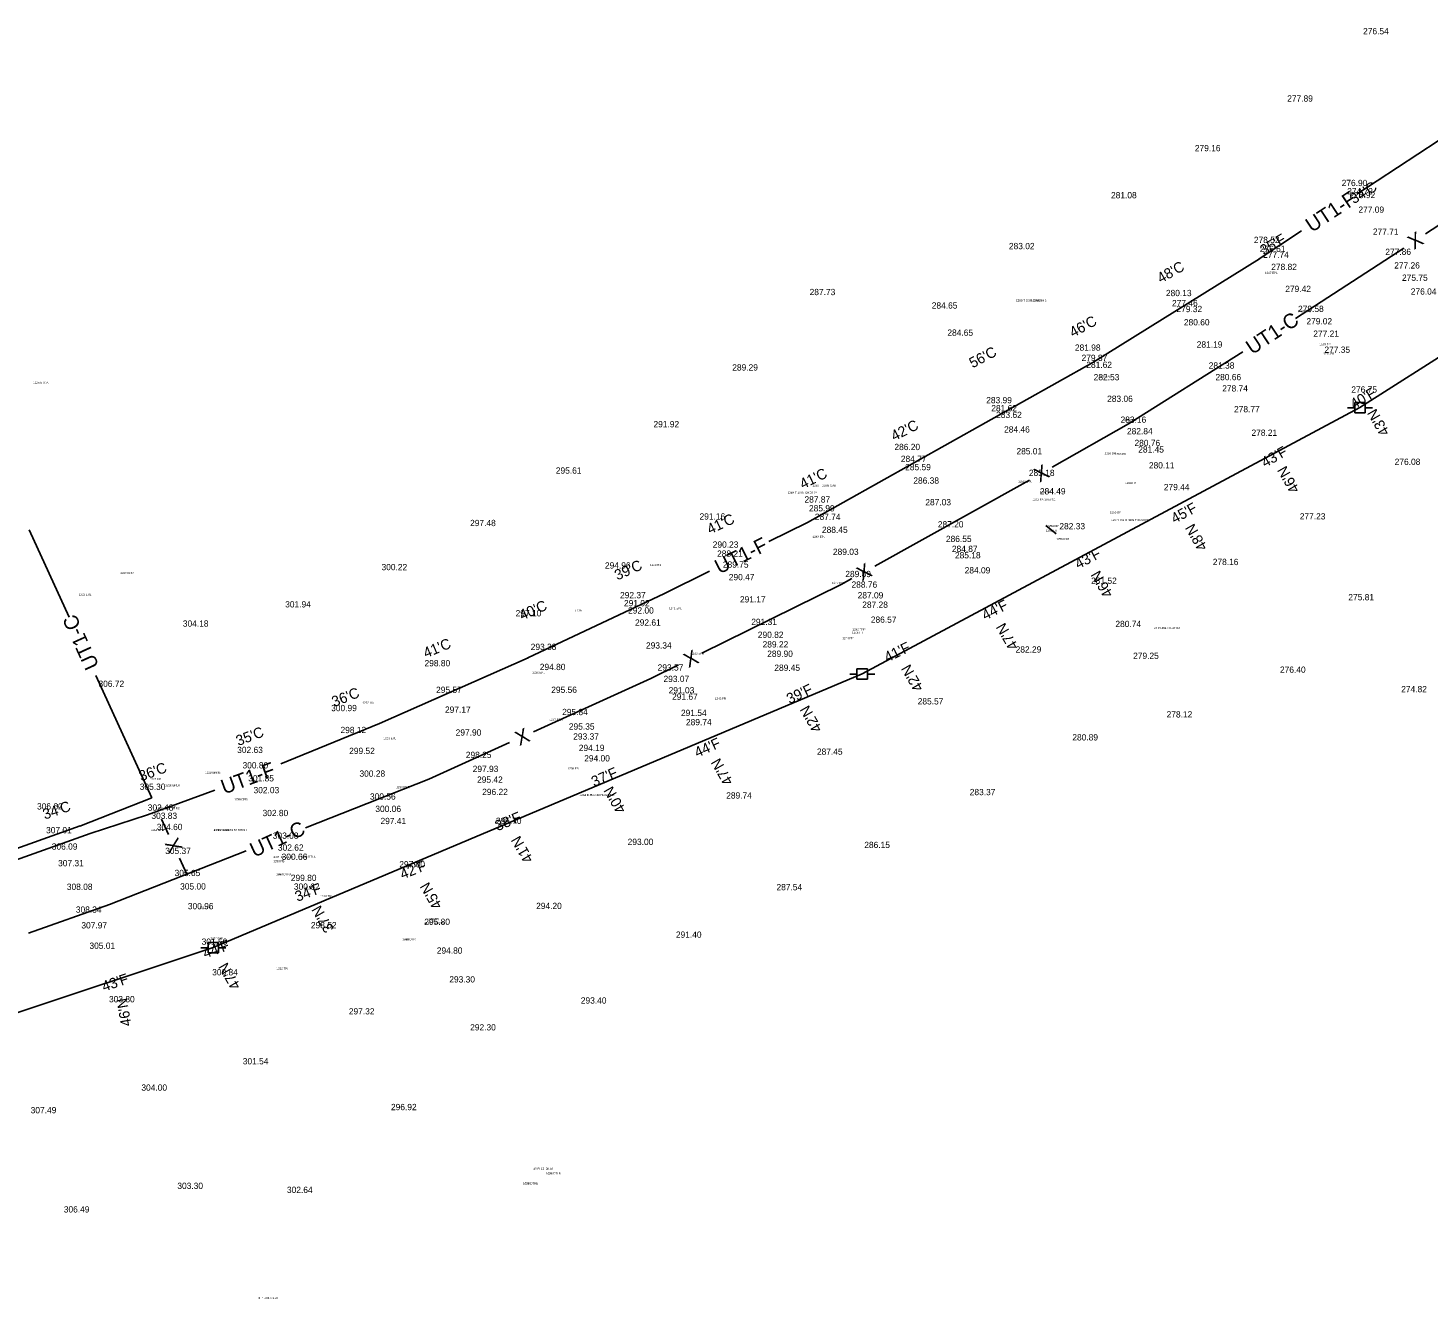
# Model space of a CAD drawing. Extents: x 49683 to 58852, y 49596 to 54801.
# Drawn here: x 51586 to 52255, y 49928 to 50535 of the extents above; entities that cross this region are included whole.
import ezdxf

# ---------------------------------------------------------------- set-up
doc = ezdxf.new("R2010")
doc.units = 0
for name, color, linetype in [('Level 10', 7, 'Continuous'), ('Level 2', 7, 'Continuous'), ('Level 3', 7, 'Continuous'), ('Level 32', 7, 'Continuous'), ('Level 4', 7, 'Continuous'), ('Level 48', 7, 'Continuous'), ('Level 51', 7, 'Continuous'), ('Level 53', 7, 'Continuous'), ('Level 56', 7, 'Continuous'), ('Level 58', 7, 'Continuous'), ('Level 59', 7, 'Continuous'), ('Level 60', 7, 'Continuous'), ('Level 61', 7, 'Continuous'), ('Level 8', 7, 'Continuous'), ('Level 9', 7, 'Continuous')]:
    doc.layers.add(name, color=color, linetype=linetype)

# ---------------------------------------------------------------- blocks, each defined once
blk = doc.blocks.new('PP')
at = {"layer": 'Level 9'}
for p, q in [((2.53, 2.45), (-2.47, 2.45)), ((-2.47, 2.45), (-2.47, -2.55)), ((2.53, -2.55), (2.53, 2.45)), ((-5.91, -0.11), (-2.44, -0.11)), ((-2.47, -2.55), (2.53, -2.55)), ((2.45, -0.11), (6.09, -0.11))]:
    blk.add_line(p, q, dxfattribs=at)

msp = doc.modelspace()

# ---------------------------------------------------------------- linework, layer by layer
at = {"layer": 'Level 10'}
for p, q in [((52222.33, 50353.9), (52441.61, 50493.85)), ((52222.33, 50353.9), (51984.4, 50226.57)), ((51674.22, 50095.74), (51984.4, 50226.57)), ((51674.22, 50095.74), (51498.02, 50037.11))]:
    msp.add_line(p, q, dxfattribs=at)
at = {"layer": 'Level 2'}
for p, q in [((52220.92, 50455.82), (52259.66, 50481.44)), ((52174.21, 50424.93), (52194.48, 50438.34)), ((52253.74, 50436.92), (52260.12, 50441.07)), ((52094.67, 50375.45), (52174.32, 50425.01)), ((52191.57, 50396.46), (52243.3, 50430.12)), ((52111.7, 50346.13), (52166.43, 50380.5)), ((51958.35, 50298.99), (52094.67, 50375.45)), ((52075.2, 50325.36), (52111.7, 50346.13)), ((51990.42, 50278.12), (52061.21, 50317.41)), ((52061.25, 50317.43), (52064.37, 50319.21)), ((51939.84, 50289.78), (51958.35, 50298.99)), ((51889.92, 50264.94), (51911.46, 50275.66)), ((51974.39, 50269.22), (51979.53, 50272.07)), ((51824.58, 50234.17), (51889.92, 50264.94)), ((51907.82, 50236.42), (51974.39, 50269.22)), ((51753.66, 50202.89), (51824.69, 50234.22)), ((51883.33, 50224.35), (51896.64, 50230.91)), ((51827.24, 50198.92), (51883.33, 50224.35)), ((51706.58, 50183.59), (51753.66, 50202.89)), ((51777.28, 50176.27), (51815.9, 50193.78)), ((51718.4, 50152.94), (51777.28, 50176.27)), ((51642.76, 50159.18), (51674.98, 50170.97)), ((51615.33, 50150.2), (51642.76, 50159.18)), ((51649.56, 50157.08), (51652.91, 50149.76)), ((51519.2, 50116.09), (51615.33, 50150.2)), ((51624.57, 50116.34), (51689.98, 50141.89)), ((51658.09, 50138.43), (51661.61, 50130.73)), ((51585.87, 50102.61), (51624.57, 50116.34))]:
    msp.add_line(p, q, dxfattribs=at)
at = {"layer": 'Level 3'}
for p, q in [((51586.25, 50295.45), (51605.36, 50253.67)), ((51618.09, 50225.85), (51644.91, 50167.23)), ((51610.53, 50153.8), (51644.91, 50167.23)), ((51517.65, 50120.85), (51610.67, 50153.85))]:
    msp.add_line(p, q, dxfattribs=at)
at = {"layer": 'Level 8'}
msp.add_line((52072.23, 50297.54), (52077.21, 50293.52), dxfattribs=at)

# ---------------------------------------------------------------- block references
at = {"layer": 'Level 10'}
for p in [(52222.33, 50353.9), (51984.4, 50226.57), (51674.22, 50095.74)]:
    msp.add_blockref('PP', p, dxfattribs=at)

# ---------------------------------------------------------------- texts
at = {"layer": 'Level 2'}
for s, rotation, p in [('UT1-F', 33.47604, (52199.33, 50437.35)), ('UT1-C', 33.47604, (52170.82, 50378.92)), ('UT1-F', 26.45366, (51916.16, 50274.09)), ('UT1-F', 20.1051, (51679.47, 50168.89)), ('UT1-C', 24.61141, (51693.8, 50138.67))]:
    msp.add_text(s, height=7, rotation=rotation, dxfattribs=at).set_placement(p)
at = {"layer": 'Level 32'}
for s, p in [('276.54', (52223.85, 50532.28)), ('277.89', (52187.59, 50500.13)), ('279.16', (52143.44, 50476.41)), ('276.90', (52213.61, 50459.74)), ('274.72', (52216.26, 50455.76)), ('275.92', (52217.39, 50453.98)), ('281.08', (52103.37, 50453.89)), ('277.09', (52221.62, 50446.98)), ('277.71', (52228.54, 50436.46)), ('283.02', (52054.56, 50429.58)), ('278.52', (52171.66, 50432.5)), ('276.61', (52174.46, 50428.23)), ('277.74', (52176.09, 50425.44)), ('277.86', (52234.49, 50426.85)), ('278.82', (52179.95, 50419.62)), ('277.26', (52238.73, 50420.34)), ('275.75', (52242.45, 50414.45)), ('287.73', (51959.29, 50407.61)), ('280.13', (52129.6, 50407.13)), ('279.42', (52186.65, 50409.09)), ('276.04', (52246.66, 50407.86)), ('284.65', (52017.68, 50401.18)), ('277.46', (52132.53, 50402.32)), ('279.32', (52134.64, 50399.48)), ('279.58', (52192.77, 50399.55)), ('284.65', (52025.15, 50388.18)), ('280.60', (52138.2, 50393.15)), ('279.02', (52196.77, 50393.62)), ('277.21', (52200.05, 50387.68)), ('281.98', (52086.1, 50381.02)), ('281.19', (52144.34, 50382.52)), ('279.87', (52089.3, 50376.15)), ('277.35', (52205.36, 50380.03)), ('289.29', (51922.32, 50371.56)), ('281.62', (52091.56, 50372.84)), ('281.38', (52150.07, 50372.49)), ('280.66', (52153.29, 50366.94)), ('282.53', (52095.08, 50366.91)), ('278.74', (52156.52, 50361.55)), ('276.75', (52218.23, 50361.01)), ('283.99', (52043.71, 50355.92)), ('283.06', (52101.51, 50356.58)), ('281.62', (52046.14, 50352.1)), ('283.62', (52048.45, 50348.9)), ('278.77', (52162.17, 50351.6)), ('291.92', (51884.65, 50344.42)), ('284.46', (52052.25, 50341.93)), ('283.16', (52107.93, 50346.57)), ('282.84', (52111, 50341.11)), ('278.21', (52170.52, 50340.35)), ('286.20', (51999.83, 50333.53)), ('280.76', (52114.58, 50335.45)), ('284.77', (52002.9, 50327.86)), ('285.01', (52058.17, 50331.48)), ('281.45', (52116.38, 50332.35)), ('295.61', (51838, 50322.27)), ('285.59', (52004.97, 50323.89)), ('285.18', (52064.11, 50321.15)), ('280.11', (52121.47, 50324.75)), ('276.08', (52238.96, 50326.46)), ('286.38', (52008.88, 50317.48)), ('279.44', (52128.62, 50314.36)), ('287.87', (51956.84, 50308.44)), ('287.03', (52014.61, 50307.11)), ('284.49', (52069.37, 50312.34)), ('291.16', (51906.69, 50300.31)), ('285.99', (51959, 50304.22)), ('287.74', (51961.81, 50300.15)), ('277.23', (52193.58, 50300.37)), ('297.48', (51797.01, 50297.19)), ('288.45', (51965.2, 50293.96)), ('287.20', (52020.58, 50296.56)), ('282.33', (52078.69, 50295.66)), ('290.23', (51912.99, 50286.87)), ('286.55', (52024.45, 50289.58)), ('288.21', (51915.06, 50282.53)), ('289.03', (51970.45, 50283.44)), ('284.87', (52027.31, 50284.82)), ('285.18', (52028.77, 50281.76)), ('300.22', (51754.67, 50276.11)), ('294.96', (51861.47, 50276.9)), ('289.75', (51917.84, 50277.32)), ('284.09', (52033.4, 50274.57)), ('278.16', (52151.99, 50278.56)), ('290.47', (51920.66, 50271.33)), ('289.09', (51976.36, 50272.8)), ('288.76', (51979.33, 50267.73)), ('281.52', (52093.84, 50269.59)), ('292.37', (51868.69, 50262.7)), ('291.17', (51925.99, 50260.69)), ('287.09', (51982.26, 50262.61)), ('275.81', (52216.81, 50261.73)), ('301.94', (51708.62, 50258.31)), ('297.10', (51818.78, 50254.07)), ('291.02', (51870.57, 50258.9)), ('292.00', (51872.53, 50255.38)), ('287.28', (51984.45, 50258.13)), ('304.18', (51659.71, 50249.1)), ('292.61', (51875.85, 50249.6)), ('291.31', (51931.41, 50249.91)), ('286.57', (51988.56, 50250.97)), ('280.74', (52105.46, 50248.92)), ('290.82', (51934.55, 50243.76)), ('293.38', (51825.99, 50237.97)), ('293.34', (51881.08, 50238.66)), ('289.22', (51936.82, 50239.17)), ('289.90', (51939.03, 50234.69)), ('282.29', (52057.78, 50236.75)), ('279.25', (52113.93, 50233.71)), ('298.80', (51775.23, 50230.17)), ('294.80', (51830.31, 50228.36)), ('293.57', (51886.66, 50228.13)), ('289.45', (51942.43, 50228)), ('276.40', (52184.12, 50227.06)), ('306.72', (51619.38, 50220.33)), ('293.07', (51889.46, 50222.65)), ('295.57', (51780.75, 50217.43)), ('295.56', (51835.8, 50217.47)), ('291.03', (51891.91, 50217.21)), ('291.67', (51893.55, 50214.15)), ('274.82', (52242.08, 50217.78)), ('300.99', (51730.6, 50208.72)), ('297.17', (51785.01, 50207.95)), ('295.84', (51841.01, 50206.83)), ('291.54', (51897.8, 50206.4)), ('285.57', (52010.95, 50211.93)), ('295.35', (51844.22, 50199.9)), ('289.74', (51900.2, 50202.01)), ('278.12', (52129.94, 50205.7)), ('298.12', (51735.06, 50198.22)), ('297.90', (51790.11, 50197.03)), ('293.37', (51846.31, 50195.14)), ('280.89', (52084.87, 50194.72)), ('302.63', (51685.68, 50188.71)), ('299.52', (51739.2, 50188.26)), ('298.25', (51794.96, 50186.34)), ('294.19', (51848.96, 50189.68)), ('287.45', (51962.79, 50187.87)), ('300.80', (51688.23, 50181.35)), ('297.93', (51798.25, 50179.63)), ('294.00', (51851.56, 50184.68)), ('301.85', (51690.97, 50175.14)), ('300.28', (51744.13, 50177.38)), ('295.42', (51800.34, 50174.5)), ('305.30', (51639.11, 50171.11)), ('302.03', (51693.5, 50169.5)), ('300.56', (51749.15, 50166.43)), ('296.22', (51802.78, 50168.61)), ('289.74', (51919.43, 50166.94)), ('283.37', (52035.83, 50168.56)), ('306.62', (51590, 50161.72)), ('302.48', (51642.93, 50161.14)), ('300.06', (51751.72, 50160.52)), ('303.83', (51644.68, 50157.23)), ('302.80', (51697.8, 50158.54)), ('297.41', (51754.18, 50154.73)), ('295.70', (51809.31, 50154.81)), ('307.01', (51594.33, 50150.35)), ('304.60', (51647.24, 50151.87)), ('303.08', (51702.7, 50147.71)), ('306.09', (51597.06, 50142.51)), ('305.37', (51651.26, 50140.45)), ('302.62', (51705.15, 50142.01)), ('293.00', (51872.32, 50144.76)), ('286.15', (51985.42, 50143.28)), ('307.31', (51600.07, 50134.58)), ('300.66', (51706.93, 50137.63)), ('297.00', (51763.17, 50134.05)), ('305.65', (51655.76, 50129.88)), ('299.80', (51711.33, 50127.55)), ('308.08', (51604.26, 50123.28)), ('305.00', (51658.41, 50123.45)), ('300.62', (51712.79, 50123.35)), ('287.54', (51943.46, 50123.1)), ('300.96', (51662.09, 50114.02)), ('294.20', (51828.56, 50114.13)), ('308.34', (51608.57, 50112.35)), ('295.80', (51775.12, 50106.54)), ('307.97', (51611.21, 50104.85)), ('298.52', (51720.91, 50104.92)), ('291.40', (51895.38, 50100.39)), ('305.01', (51615.06, 50095.1)), ('301.50', (51668.7, 50097.03)), ('294.80', (51781.09, 50092.78)), ('300.84', (51673.72, 50082.42)), ('293.30', (51787.07, 50079.02)), ('303.80', (51624.42, 50069.53)), ('293.40', (51849.94, 50068.93)), ('297.32', (51739.04, 50063.74)), ('292.30', (51797.03, 50056.09)), ('301.54', (51688.35, 50039.86)), ('304.00', (51639.89, 50027.27)), ('307.49', (51586.97, 50016.49)), ('296.92', (51759.19, 50017.98)), ('303.30', (51657.08, 49980.32)), ('302.64', (51709.47, 49978.39)), ('306.49', (51602.79, 49969.06))]:
    msp.add_text(s, height=3, dxfattribs=at).set_placement(p)
at = {"layer": 'Level 4'}
for s, rotation, p in [('X', 33.05568, (52248.14, 50429.1)), ('X', 29.63146, (52069.14, 50317.89)), ('X', 29.03259, (51984.29, 50270.71)), ('UT1-C', 114.58439, (51619.82, 50230.49)), ('X', 26.22879, (51901.33, 50229.32)), ('X', 24.39066, (51820.53, 50192.04)), ('X', 114.58439, (51659.82, 50143.07))]:
    msp.add_text(s, height=7, rotation=rotation, dxfattribs=at).set_placement(p)
at = {"layer": 'Level 48'}
for s, rotation, p in [("34'C", 31.24615, (52219.41, 50451.04)), ("35'F", 30.37114, (52176.45, 50426.49)), ("48'C", 29.49614, (52127.19, 50413.14)), ("46'C", 28.62113, (52085.2, 50387.24)), ("56'C", 27.74616, (52037.2, 50372.6)), ("40'F", 30.37114, (52219.54, 50352.97)), ("43'N", 119.91701, (52236.69, 50342.04)), ("42'C", 26.87112, (51999.77, 50337.74)), ("43'F", 29.49616, (52177.01, 50325.05)), ("41'C", 25.9962, (51956.06, 50314.79)), ("46'N", 119.91701, (52193.67, 50314.71)), ("45'F", 28.62116, (52133.77, 50298.24)), ("41'C", 25.12117, (51911.67, 50293.16)), ("48'N", 119.91701, (52149.63, 50287.13)), ("43'F", 27.74614, (52087.73, 50276.55)), ("39'C", 24.24618, (51867.42, 50271.18)), ("46'N", 119.91701, (52104.55, 50264.71)), ("40'C", 23.37116, (51821.86, 50252.06)), ("44'F", 26.87117, (52043.2, 50252.04)), ("47'N", 119.91701, (52059.22, 50239.7)), ("41'C", 22.49617, (51775.89, 50234.01)), ("41'F", 25.99616, (51996.44, 50231.97)), ("42'N", 119.91701, (52013.88, 50219.85)), ("36'C", 21.62118, (51732.04, 50210.67)), ("39'F", 25.12119, (51949.71, 50212.03)), ("42'N", 119.91701, (51965.46, 50200.26)), ("35'C", 20.7462, (51686.22, 50192.03)), ("44'F", 24.24616, (51905.58, 50186.45)), ("36'C", 19.87119, (51639.74, 50175.14)), ("47'N", 119.91701, (51922.96, 50175)), ("37'F", 23.37116, (51856.26, 50172.47)), ("40'N", 119.91701, (51871.7, 50161.59)), ("34'C", 18.99618, (51593.73, 50156.85)), ("38'F", 22.49617, (51810.13, 50151.32)), ("41'N", 119.91701, (51827.4, 50137.88)), ("42'F", 21.62119, (51764.71, 50128.23)), ("34'F", 20.74622, (51714.43, 50117.55)), ("45'N", 119.91701, (51783.87, 50115.71)), ("37'N", 119.91701, (51732.09, 50104.62)), ("44'F", 19.87119, (51670.35, 50090.45)), ("43'F", 18.99623, (51622.05, 50074.59)), ("47'N", 119.91701, (51687.53, 50077.3)), ("46'N", 99.63668, (51635.14, 50058.5))]:
    msp.add_text(s, height=5, rotation=rotation, dxfattribs=at).set_placement(p)
at = {"layer": 'Level 51'}
for s, p in [('23 PI 494+33.47 C2', (52123.93, 50247.98)), ('42 PI 10+00', (51674.47, 50151.38)), ('7 POC 494+74.88 DITCH', (51674.47, 50151.38)), ('43 PI 10+31.27', (51702.96, 50138.51)), ('44 PI 11+09.96', (51775.04, 50106.93)), ('45 PI 12+38.46', (51827.26, 49989.51)), ('6 PI 494+72.95', (51695.9, 49927.72))]:
    msp.add_text(s, height=1, dxfattribs=at).set_placement(p)
at = {"layer": 'Level 53'}
for s, p in [('1267 EPL', (52176.97, 50417.76)), ('1268 EPR', (52192.62, 50399.34)), ('1225 ERRA', (51588.14, 50365.28)), ('1265 EPL', (52097.21, 50368.15)), ('1261 EPR', (52109.21, 50347.41)), ('1251 EPR', (52059, 50317.98)), ('1248 EPL', (51960.69, 50291.57)), ('1226 ERR', (51629.77, 50274.29)), ('1247 EPR', (51969.98, 50269.55)), ('1223 ERL', (51609.89, 50263.93)), ('1241 EPL', (51892.1, 50257.44)), ('1242 EPR', (51902.62, 50235.73)), ('1238 EPL', (51826.71, 50226.65)), ('1237 EPR', (51834.95, 50204.07)), ('1231 EPL', (51755.62, 50195.29)), ('1227 ERRB', (51670.38, 50178.85)), ('1221 ERLA', (51651.27, 50172.81)), ('1233 EPR', (51761.7, 50171.91)), ('1230 EPL', (51684.3, 50166.06)), ('1217 EPL', (51644.4, 50151.45))]:
    msp.add_text(s, height=1, dxfattribs=at).set_placement(p)
at = {"layer": 'Level 56'}
for s, p in [('1263 PB', (52105.27, 50331.14)), ('1262 PA 18IN RC', (52065.82, 50309.34)), ('1282 PA 24 IN RC', (51646.91, 50161.84)), ('1283 PB', (51702.96, 50136.51))]:
    msp.add_text(s, height=1, dxfattribs=at).set_placement(p)
at = {"layer": 'Level 58'}
for s, p in [('1270 FR', (52204.78, 50379.12)), ('1260 DPB', (52109.21, 50347.41)), ('1259 DP', (52100.29, 50331.5)), ('1252 DPA', (52059, 50317.98)), ('1264 FR', (52110.13, 50317.32)), ('1253 DP', (52069.29, 50313.04)), ('1258 DP', (52102.84, 50303.33)), ('1254 DP', (52072.89, 50296.75)), ('1257 FRA O 48IN HOGWIRE', (52103.43, 50299.65)), ('1255 FR', (52072.23, 50294.54)), ('1256 FRB', (52077.21, 50290.52)), ('1246 FR', (51979.55, 50245.78)), ('1243 FR', (51914.03, 50214.29)), ('1228 DP', (51670.38, 50178.85)), ('1236 FR', (51843.63, 50180.86)), ('1220 DP', (51651.27, 50172.81)), ('1219 DP', (51650.89, 50162.41)), ('1229 DPB', (51684.3, 50166.06)), ('1235 FRA O 48 HOGWIRE', (51849.3, 50168.17)), ('1218 DPA', (51644.4, 50151.45))]:
    msp.add_text(s, height=1, dxfattribs=at).set_placement(p)
at = {"layer": 'Level 59'}
for s, p in [('1269 PP', (52203, 50383.66)), ('1244 PP', (51974.93, 50243.12)), ('1245 TPP', (51979.81, 50247.25)), ('1222 PP', (51643.93, 50175.76)), ('1213 PP', (51667.68, 50114.34)), ('1214 GW', (51672.86, 50099.69))]:
    msp.add_text(s, height=1, dxfattribs=at).set_placement(p)
at = {"layer": 'Level 60'}
for s, p in [('1593 DTLA', (51716.14, 50138.63)), ('1666 DTLA', (51716.14, 50138.63)), ('1594 DTRA', (51704.36, 50130.26)), ('1667 DTRA', (51704.36, 50130.26)), ('1595 DTL', (51776.62, 50108.7)), ('1668 DTL', (51776.62, 50108.7)), ('1596 DTR', (51764.63, 50099.16)), ('1669 DTR', (51764.63, 50099.16)), ('1597 DTRB', (51822.31, 49982.41)), ('1670 DTRB', (51822.31, 49982.41)), ('1598 DTLB', (51833.3, 49987.23)), ('1671 DTLB', (51833.3, 49987.23))]:
    msp.add_text(s, height=1, dxfattribs=at).set_placement(p)
at = {"layer": 'Level 61'}
for s, p in [('1266 T 36 IN OAK', (52057.94, 50404.56)), ('1709 T 36IN OAK BM 3', (52057.94, 50404.56)), ('1250 T 24 IN OAK', (51960.7, 50316.06)), ('1249 T 18 IN CHERRY', (51948.78, 50312.69)), ('1240 HB', (51883, 50278.13)), ('1239 H', (51847.19, 50256.26)), ('1232 HA', (51745.6, 50212.27)), ('1234 TRB', (51849.3, 50168.17)), ('1216 TR', (51725.48, 50119.82)), ('1215 TR', (51704.47, 50085.19))]:
    msp.add_text(s, height=1, dxfattribs=at).set_placement(p)

doc.saveas('drawing.dxf')
